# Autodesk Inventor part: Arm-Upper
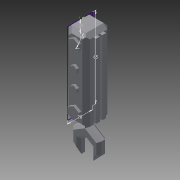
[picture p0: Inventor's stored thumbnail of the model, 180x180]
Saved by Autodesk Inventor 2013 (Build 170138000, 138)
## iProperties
Created: 2013-03
Part Number: Arm-Upper
Material: Generic
Document SubType Name: Modeling
Designer: frankenteddy
Density: 1 g/cm^3
Author: frankenteddy
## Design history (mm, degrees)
sketch "Sketch1"
  geometry: L1 (-10, 32.5)-(10, 32.5); L2 (10, 32.5)-(10, -32.5); L3 (10, -32.5)-(-10, -32.5); L4 (-10, -32.5)-(-10, 32.5); L5 (0, 22.5)-(0, 12.5); L6 (0, 32.5)-(3.5, 32.5); L7 (0, -32.5)-(0, 32.5); A1 r 5 centre (0, 17.5) between (0, 12.5) and (0, 22.5); 3 further points
  constraints: 14 end point, 4 midpoint, 3 parallel, 2 point on circle, 1 centre point, 1 coincident, 1 horizontal, 1 horizontal alignment, 1 perpendicular, 1 vertical alignment
  dimensions: "d0" = 20 distance of L2.end L3.end; "d1" = 65 distance of L1.end L2.end; "d4" = 10 diameter of A1; "d5" = 10 distance from line of L5.start L1
extrude "Extrusion1" new body sketch "Sketch1" distance "d2" = 15; taper "d3" = 0 deg
extrude "Extrusion3" join sketch "Sketch1" distance "d9" = 2; taper "d10" = 0 deg
revolve "Revolution2" stored, may be unused: angle "d11" = 90 deg
sketch "Sketch2"
  geometry: L1 (0, 0)-(-17, 0) reference; L2 (0, 65)-(0, 0) reference; L3 (0, 65)-(-15.5, 65); L4 (-15.5, 65)-(-15.5, 0); L5 (-15.5, 0)-(0, 0); L6 (0, 0)-(0, 65); L7 (-15.5, 0)-(-17, 0); L8 (-17, 0)-(-17, 65); L9 (-17, 65)-(-15.5, 65); L10 (-15.5, 65)-(-15.5, 0); L11 (-8.25, 61)-(-4.146, 58.631); L12 (-4.146, 58.631)-(-4.146, 53.892); L13 (-4.146, 53.892)-(-8.25, 51.522); L14 (-8.25, 51.522)-(-12.354, 53.892); L15 (-12.354, 53.892)-(-12.354, 58.631); L16 (-12.354, 58.631)-(-8.25, 61); L17 (-8.25, 28.5)-(-5.721, 27.04); L18 (-5.721, 27.04)-(-5.721, 24.119); L19 (-5.721, 24.119)-(-8.25, 22.659); L20 (-8.25, 22.659)-(-10.779, 24.119); L21 (-10.779, 24.119)-(-10.779, 27.04); L22 (-10.779, 27.04)-(-8.25, 28.5); L23 (-8.25, 14.139)-(-3.86, 11.604); L24 (-3.86, 11.604)-(-3.86, 6.535); L25 (-3.86, 6.535)-(-8.25, 4); L26 (-8.25, 4)-(-12.64, 6.535); L27 (-12.64, 6.535)-(-12.64, 11.604); L28 (-12.64, 11.604)-(-8.25, 14.139); L29 (0, 32.5)-(-17, 32.5); L30 (-10.779, 37.96)-(-10.779, 40.881); L31 (-5.721, 40.881)-(-5.721, 37.96); L32 (-8.25, 36.5)-(-10.779, 37.96); L33 (-5.721, 37.96)-(-8.25, 36.5); L34 (-10.779, 40.881)-(-8.25, 42.341); L35 (-8.25, 42.341)-(-5.721, 40.881); 5 further points
  constraints: 66 end point, 4 parallel, 2 horizontal, 2 midpoint, 2 perpendicular, 1 point on line, 52 other
  dimensions: "d16" = 4 distance from line of L11.start L3; "d17" = 4 distance from line of L1 L25.end; "d19" = 8.25 distance from line of point (-8.25, 56.261) L2; "d20" = 8.25 distance from line of point (-8.25, 25.58) L2; "d21" = 8.25 distance from line of point (-8.25, 9.069) L2; "d46" = 4 distance from line of L17.start L29; "d47" = 8.25 distance from line of point (-8.25, 39.42) L2; "d48" = 4 distance from line of L29 L32.start
extrude "Extrusion4" join sketch "Sketch2" distance "d22" = 2; taper "d23" = 0 deg
chamfer "Chamfer1" distance "d24" = 3; stored, may be unused: second distance "d25" = 2, angle "d26" = 45 deg
chamfer "Chamfer2" distance "d33" = 3; stored, may be unused: second distance "d34" = 2, angle "d35" = 45 deg
sketch "Sketch4"
  geometry: L1 (-29.5, -7)-(-29.5, 7) reference; L2 (29.5, -7)-(-29.5, -7) reference; L3 (29.5, 7)-(29.5, -7) reference; L4 (-29.5, 7)-(29.5, 7) reference; L5 (-29.5, 4)-(29.5, 4); L6 (29.5, 4)-(29.5, 1); L7 (29.5, 1)-(-29.5, 1); L8 (-29.5, 1)-(-29.5, 4); L9 (29.5, -4)-(-29.5, -4); L10 (-29.5, -4)-(-29.5, -1); L11 (-29.5, -1)-(29.5, -1); L12 (29.5, -1)-(29.5, -4); 1 further point
  constraints: 16 end point, 4 parallel, 4 point on line, 2 horizontal, 2 perpendicular
  dimensions: "d36" = 3 distance of L5.end L6.end; "d37" = 3 distance of L9.end L10.end; "d38" = 3 distance between parallel lines of L9 L2; "d39" = 3 distance between parallel lines of L4 L5
extrude "Extrusion6" join sketch "Sketch4" distance "d40" = 2; taper "d41" = 0 deg
workplane "Work Plane1"
sketch "Sketch6"
  geometry: L1 (0, 0)-(-15, 0) reference; L2 (-15, 0)-(-15, -65); L3 (-15, -65)-(0, -65); L4 (0, -65)-(0, 0) reference; L5 (-5.5, -69)-(-9.5, -69); L6 (-5.5, -65)-(-5.5, -69); L7 (-9.5, -69)-(-9.5, -65); L8 (-7.5, -69)-(-7.5, -65); L9 (-9.5, -69)-(-18.755, -74.602); L10 (-7.5, -69)-(-7.5, -77.385); L11 (-5.5, -69)-(3.755, -74.602); L12 (-12.325, -80.305)-(-7.5, -77.385); L13 (-2.675, -80.305)-(-7.5, -77.385); L14 (-18.755, -74.602)-(-18.755, -84.453); L15 (3.755, -74.602)-(3.755, -84.453); L16 (-18.755, -84.453)-(-12.325, -91.194); L17 (-12.325, -91.194)-(-12.325, -80.305); L18 (-2.675, -91.194)-(-2.675, -80.305); L19 (3.755, -84.453)-(-2.675, -91.194); L20 (-7.5, 0)-(-7.5, -65); L21 (-9.5, -65)-(-5.5, -65); 1 further point
  constraints: 42 end point, 8 parallel, 4 symmetric about line, 3 midpoint, 2 horizontal, 2 perpendicular, 1 collinear, 1 vertical
  dimensions: "d49" = 65 distance of L2.end L1.end; "d51" = 15 distance of L2.end L3.end; "d52" = 4 distance of L5.start L5.end; "d53" = 4 distance of L6.start L5.start
extrude "Extrusion8" join sketch "Sketch6" stored distance "d54" = 7; taper "d55" = 0 deg
chamfer "Chamfer3" distance "d56" = 2; stored, may be unused: second distance "d57" = 2, angle "d58" = 45 deg
chamfer "Chamfer4" distance "d59" = 2; stored, may be unused: second distance "d60" = 2, angle "d61" = 45 deg
chamfer "Chamfer5" distance "d62" = 2; stored, may be unused: second distance "d63" = 2, angle "d64" = 45 deg
chamfer "Chamfer6" distance "d65" = 2; stored, may be unused: second distance "d66" = 2, angle "d67" = 45 deg
chamfer "Chamfer7" distance "d68" = 2; stored, may be unused: second distance "d69" = 2, angle "d70" = 45 deg
chamfer "Chamfer8" distance "d71" = 2; stored, may be unused: second distance "d72" = 2, angle "d73" = 45 deg
body "Solid1"
